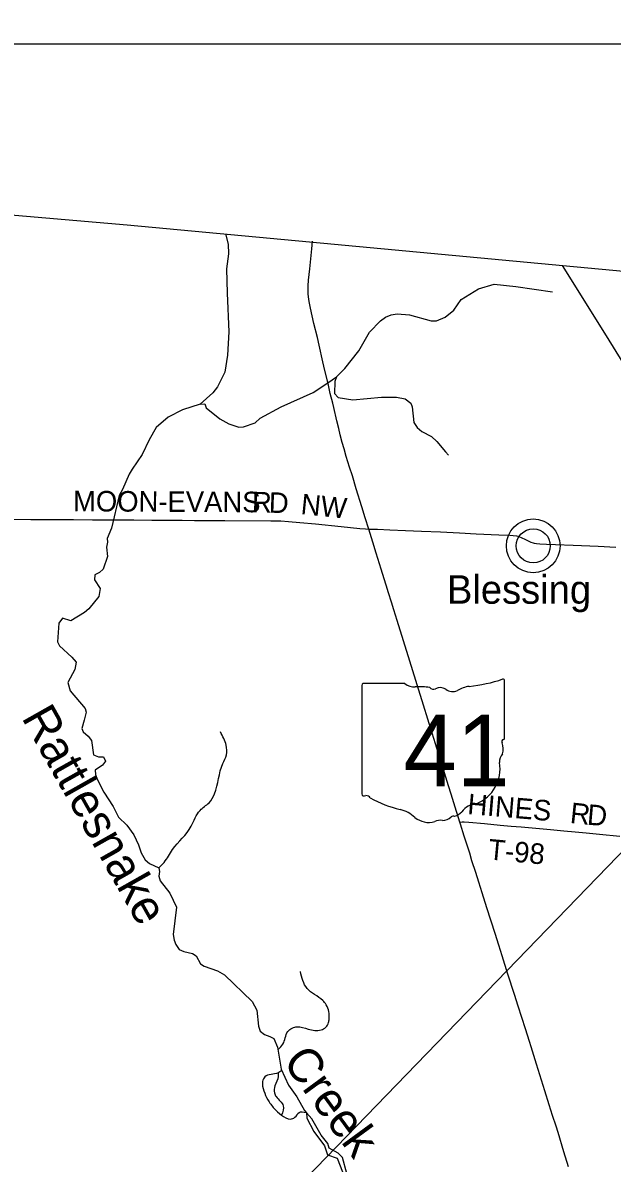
# Model space of a CAD drawing. Extents: x -49 to -8.2, y 9.4 to 23.5.
# Drawn here: x -41.499 to -40.683, y 19.456 to 21.033 of the extents above; entities that cross this region are included whole.
import ezdxf

# ---------------------------------------------------------------- set-up
doc = ezdxf.new("R2010")
doc.units = 0
for name, color, linetype in [('GM_X_Adjacent_County', 7, 'Continuous'), ('GM_X_County_Road', 7, 'Continuous'), ('GM_X_County_Road_Text', 7, 'Continuous'), ('GM_X_Major_River', 7, 'Continuous'), ('GM_X_Major_River_Text', 7, 'Continuous'), ('GM_X_Minor_River', 7, 'Continuous'), ('GM_X_Rail_Line', 7, 'Continuous'), ('GM_X_State_Route', 7, 'Continuous'), ('GM_X_State_Shield', 7, 'Continuous'), ('GM_X_Township_Road', 7, 'Continuous'), ('GM_X_Township_Road_Text', 7, 'Continuous'), ('GM_X_Unincorporated', 7, 'Continuous'), ('GM_X_Unincorporated_Text', 7, 'Continuous'), ('SC_Scratch1', 7, 'Continuous')]:
    doc.layers.add(name, color=color, linetype=linetype)

msp = doc.modelspace()

# ---------------------------------------------------------------- linework, layer by layer
at = {"layer": 'GM_X_Adjacent_County'}
for points in [[(-42.0989, 21.0039), (-42.1133, 20.8458), (-42.1156, 20.8206), (-41.9021, 20.8017), (-41.5804, 20.7732), (-41.3548, 20.7539), (-41.1025, 20.7304), (-40.4155, 20.6663), (-39.4895, 20.588)], [(-42.0989, 21.0039), (-42.1133, 20.8458), (-42.1156, 20.8206), (-41.9021, 20.8017), (-41.5804, 20.7732), (-41.3548, 20.7539), (-41.1025, 20.7304), (-40.4155, 20.6663), (-39.4895, 20.588)], [(-39.4895, 20.588), (-39.4895, 21.0039), (-42.0989, 21.0039)], [(-39.4895, 20.588), (-39.4895, 21.0039), (-42.0989, 21.0039)]]:
    msp.add_lwpolyline(points, dxfattribs=at)
at = {"layer": 'GM_X_County_Road'}
for points in [[(-41.5222, 20.3465), (-41.4881, 20.3462), (-41.454, 20.3461), (-41.4291, 20.346), (-41.4027, 20.3458), (-41.3888, 20.3457), (-41.3764, 20.3456), (-41.3624, 20.3456), (-41.3453, 20.3455), (-41.3205, 20.3453), (-41.2786, 20.3451), (-41.2615, 20.3449), (-41.2491, 20.3449), (-41.2196, 20.3447), (-41.156, 20.3444), (-41.142, 20.3441), (-41.1312, 20.3435), (-41.1157, 20.3421), (-41.0941, 20.34), (-41.0586, 20.3363), (-41.0324, 20.3338), (-41.0246, 20.3331), (-41.0203, 20.3327)], [(-41.0203, 20.3327), (-41.008, 20.3329), (-40.9909, 20.332), (-40.9692, 20.3311), (-40.9474, 20.3301), (-40.921, 20.3289), (-40.8947, 20.3275), (-40.8714, 20.3263), (-40.8403, 20.3251), (-40.8248, 20.3245), (-40.8202, 20.3241), (-40.8156, 20.3234), (-40.8126, 20.3226), (-40.8082, 20.321), (-40.804, 20.319), (-40.7985, 20.3161), (-40.7956, 20.3148), (-40.7927, 20.3138), (-40.7912, 20.3134), (-40.7882, 20.3128), (-40.7835, 20.3123), (-40.7742, 20.3119), (-40.7618, 20.3114), (-40.737, 20.3105), (-40.7028, 20.3091), (-40.678, 20.308)]]:
    msp.add_lwpolyline(points, dxfattribs=at)
at = {"layer": 'GM_X_Major_River'}
for points in [[(-41.2184, 20.7413), (-41.2148, 20.7272), (-41.2145, 20.7139), (-41.2171, 20.6928), (-41.2165, 20.6595), (-41.214, 20.6056), (-41.216, 20.5733), (-41.2195, 20.5502), (-41.2299, 20.5298), (-41.2362, 20.5213), (-41.2537, 20.5056), (-41.2783, 20.4978), (-41.2982, 20.4876), (-41.3144, 20.4735), (-41.3245, 20.4565), (-41.3339, 20.4362), (-41.348, 20.4156), (-41.352, 20.409), (-41.3612, 20.3877)], [(-41.3612, 20.3877), (-41.3659, 20.3793), (-41.3763, 20.3341), (-41.3825, 20.3197), (-41.3818, 20.3146), (-41.3834, 20.308), (-41.382, 20.2952), (-41.3882, 20.2776), (-41.393, 20.2728), (-41.3996, 20.2694), (-41.3999, 20.2628), (-41.3921, 20.2505), (-41.3941, 20.2397), (-41.4078, 20.2224), (-41.4138, 20.2177), (-41.4328, 20.2062), (-41.4445, 20.2095), (-41.4493, 20.2027), (-41.4512, 20.1769), (-41.4486, 20.1714), (-41.4314, 20.1555), (-41.4256, 20.1488), (-41.427, 20.1385), (-41.437, 20.1206), (-41.4339, 20.1092), (-41.4131, 20.0846), (-41.4117, 20.0795), (-41.4144, 20.0687), (-41.4175, 20.057), (-41.4157, 20.0522), (-41.4086, 20.0463), (-41.4043, 20.0403), (-41.4012, 20.0207), (-41.3946, 20.018), (-41.3876, 20.0178), (-41.3849, 20.0118), (-41.3891, 20.0064), (-41.3992, 19.9994), (-41.3988, 19.9934), (-41.3961, 19.9871), (-41.387, 19.9691), (-41.3743, 19.9491), (-41.3669, 19.9345)], [(-41.3669, 19.9345), (-41.3551, 19.9231), (-41.3457, 19.9101), (-41.339, 19.8962), (-41.3356, 19.8848), (-41.33, 19.8753), (-41.3238, 19.8701), (-41.311, 19.8644), (-41.3098, 19.8593), (-41.3108, 19.8526), (-41.3092, 19.8462), (-41.2958, 19.8294), (-41.2866, 19.81), (-41.291, 19.7722), (-41.2895, 19.7641), (-41.2873, 19.758), (-41.2826, 19.7515), (-41.2764, 19.7484), (-41.2643, 19.7459), (-41.2592, 19.7427), (-41.2534, 19.7316), (-41.2483, 19.7282), (-41.2299, 19.722), (-41.2199, 19.7163), (-41.1819, 19.6793), (-41.1751, 19.6673), (-41.1728, 19.6451), (-41.1708, 19.6384), (-41.1645, 19.6338), (-41.1572, 19.6309), (-41.1519, 19.6283), (-41.1465, 19.6163), (-41.1415, 19.5855), (-41.1312, 19.5638), (-41.1199, 19.5473), (-41.1091, 19.5284), (-41.1064, 19.5254)], [(-41.0507, 19.4412), (-41.0568, 19.4636), (-41.0628, 19.4694), (-41.0751, 19.4763), (-41.0767, 19.4827), (-41.0861, 19.4943), (-41.0989, 19.517), (-41.1064, 19.5254)], [(-41.1064, 19.5254), (-41.1061, 19.518), (-41.0963, 19.4993), (-41.0817, 19.4797), (-41.0772, 19.4673), (-41.0642, 19.4627), (-41.0565, 19.4439)]]:
    msp.add_lwpolyline(points, dxfattribs=at)
at = {"layer": 'GM_X_Minor_River'}
for points in [[(-41.2537, 20.5056), (-41.2474, 20.5064), (-41.2454, 20.5007), (-41.2265, 20.4854), (-41.214, 20.4787), (-41.2003, 20.4741), (-41.1936, 20.4744), (-41.1777, 20.4798), (-41.1707, 20.4863), (-41.1416, 20.5019), (-41.0972, 20.5221), (-41.0771, 20.5351), (-41.0647, 20.5436), (-41.0533, 20.5553), (-41.0339, 20.5795), (-41.0192, 20.6052), (-41.0041, 20.6211), (-40.9971, 20.6263), (-40.9893, 20.6295), (-40.9808, 20.6306), (-40.9638, 20.6294), (-40.9339, 20.6211), (-40.9264, 20.6209), (-40.9144, 20.6263), (-40.9024, 20.6359), (-40.8925, 20.6505), (-40.8682, 20.6653), (-40.8464, 20.6719), (-40.8165, 20.6685), (-40.7658, 20.661)], [(-41.0647, 20.5436), (-41.0672, 20.5372), (-41.0679, 20.5203), (-41.0624, 20.5151), (-41.0424, 20.5118), (-41.0028, 20.5154), (-40.982, 20.5153), (-40.9699, 20.5133)], [(-40.9699, 20.5133), (-40.962, 20.5069), (-40.9601, 20.5021), (-40.9576, 20.4805), (-40.9532, 20.4734), (-40.9466, 20.4679), (-40.9332, 20.461), (-40.9259, 20.4543), (-40.9142, 20.4397), (-40.9098, 20.4354)]]:
    msp.add_lwpolyline(points, dxfattribs=at)
for points in [[(-41.311, 19.8644), (-41.3037, 19.8718), (-41.2919, 19.8895), (-41.266, 19.9217), (-41.2539, 19.9438), (-41.2414, 19.9544), (-41.2338, 19.9667), (-41.2224, 20.0086), (-41.2174, 20.0207), (-41.2177, 20.0338), (-41.2257, 20.0524)], [(-41.1458, 19.6131), (-41.139, 19.6204), (-41.1323, 19.6378), (-41.1263, 19.6426), (-41.1192, 19.6444), (-41.1043, 19.6411), (-41.0861, 19.6401), (-41.0797, 19.6437), (-41.0759, 19.6503), (-41.0751, 19.655), (-41.0791, 19.6748), (-41.084, 19.6807), (-41.1057, 19.6975), (-41.1149, 19.7207)], [(-41.1408, 19.584), (-41.1459, 19.5806), (-41.1641, 19.575), (-41.1673, 19.5687), (-41.1655, 19.5558), (-41.1601, 19.5435), (-41.1513, 19.5315), (-41.1409, 19.5221), (-41.1288, 19.5166), (-41.1224, 19.5192), (-41.1168, 19.5258), (-41.1069, 19.5259)], [(-41.1459, 19.5806), (-41.1455, 19.5757), (-41.1503, 19.5626), (-41.1508, 19.5529), (-41.1485, 19.5478), (-41.1387, 19.535), (-41.1409, 19.5221)]]:
    msp.add_spline(points, degree=3, dxfattribs=at)
at = {"layer": 'GM_X_Rail_Line'}
msp.add_lwpolyline([(-40.6679, 20.5631), (-40.6912, 20.6002), (-40.7519, 20.6976)], dxfattribs=at)
at = {"layer": 'GM_X_State_Route'}
msp.add_lwpolyline([(-40.7435, 19.4504), (-40.7499, 19.4712), (-40.7581, 19.4979), (-40.7609, 19.5068), (-40.7656, 19.5216), (-40.7703, 19.5364), (-40.7763, 19.5557), (-40.7878, 19.5928), (-40.7952, 19.6166), (-40.7976, 19.6239), (-40.8034, 19.6417), (-40.8134, 19.6727), (-40.8186, 19.689), (-40.8275, 19.7171), (-40.8355, 19.7423), (-40.8402, 19.7571), (-40.8454, 19.7734), (-40.8568, 19.8089), (-40.8632, 19.8297), (-40.8679, 19.8445), (-40.8721, 19.8578), (-40.8773, 19.8741), (-40.8805, 19.8845), (-40.888, 19.9082), (-40.8931, 19.9246), (-40.894, 19.9276), (-40.9005, 19.9483), (-40.9061, 19.966), (-40.9098, 19.9779), (-40.9192, 20.0075), (-40.9278, 20.0357), (-40.9324, 20.0506), (-40.9366, 20.064), (-40.9461, 20.0951), (-40.9512, 20.1115), (-40.9549, 20.1233), (-40.9634, 20.15), (-40.9807, 20.2064), (-40.9854, 20.2212), (-40.9886, 20.2316), (-40.9929, 20.2449), (-40.9962, 20.2552), (-40.999, 20.2641), (-41.0031, 20.2775), (-41.01, 20.2997), (-41.0147, 20.3146), (-41.0203, 20.3327), (-41.0252, 20.3487), (-41.0298, 20.3635), (-41.0375, 20.3888), (-41.0429, 20.4066), (-41.0467, 20.4185), (-41.0513, 20.4333), (-41.0544, 20.4438), (-41.0569, 20.4527), (-41.0597, 20.4632), (-41.0619, 20.4723), (-41.0644, 20.4829), (-41.0688, 20.501), (-41.0702, 20.5071), (-41.0735, 20.5206), (-41.0766, 20.5343), (-41.0809, 20.5524), (-41.0837, 20.5645), (-41.089, 20.5872), (-41.0914, 20.5978), (-41.0961, 20.6174), (-41.101, 20.6386), (-41.1029, 20.6478), (-41.1038, 20.654), (-41.1042, 20.6586), (-41.1043, 20.6633), (-41.1041, 20.6696), (-41.1035, 20.6773), (-41.1019, 20.6928), (-41.0991, 20.7206), (-41.098, 20.7311)], dxfattribs=at)
at = {"layer": 'GM_X_State_Shield'}
for p, q in [((-41.0299, 20.1167), (-41.0299, 19.9666)), ((-40.9701, 20.1192), (-41.028, 20.1192)), ((-40.8322, 20.0444), (-40.8322, 20.123)), ((-40.8322, 20.0445), (-40.8322, 20.0444))]:
    msp.add_line(p, q, dxfattribs=at)
for centre, radius, start, end in [((-41.0277, 20.117), 0.00229, 98.1301, 188.1301), ((-40.9563, 20.1367), 0.0222, 231.6195, 271.1119), ((-40.9026, 20.3239), 0.2097, 275.8445, 288.9065), ((-40.8344, 20.1233), 0.0022, 351.8621, 97.738), ((-40.9489, 20.035), 0.0798, 80.4867, 94.9883), ((-40.9308, 20.1178), 0.00641, 219.7921, 297.1024), ((-40.9214, 20.1004), 0.0133, 54.4667, 119.1411), ((-40.9042, 20.1242), 0.016, 233.8562, 294.8282), ((-40.8759, 20.0734), 0.0422, 97.3462, 120.7689), ((-40.8327, 20.0387), 0.00341, 107.944, 210.337), ((-40.8544, 20.0288), 0.0205, 340.033, 23.6496), ((-40.8345, 20.0441), 0.00236, 289.6038, 7.7341), ((-40.8243, 20.0116), 0.0149, 136.8065, 186.9296), ((-40.8909, 20.0016), 0.0525, 292.3089, 8.9858), ((-41.0276, 19.9662), 0.00231, 171.9584, 258.3066), ((-41.0273, 19.9816), 0.0176, 267.339, 280.6039), ((-41.0237, 19.9579), 0.00636, 29.7484, 93.2717), ((-40.9434, 20.0928), 0.1514, 240.4129, 257.1985), ((-40.9885, 19.8991), 0.0474, 47.1842, 75.836), ((-40.8687, 19.9244), 0.0287, 94.4031, 142.5768), ((-40.9373, 19.9572), 0.0301, 230.7004, 286.2918), ((-40.9199, 19.9053), 0.0247, 85.6951, 111.2099), ((-40.9177, 19.9459), 0.016, 268.777, 315.5493), ((-40.9032, 19.9314), 0.00451, 65.7517, 132.6484), ((-40.9051, 19.952), 0.0169, 282.8732, 323.2771)]:
    msp.add_arc(centre, radius, start, end, dxfattribs=at)
at = {"layer": 'GM_X_Township_Road'}
msp.add_lwpolyline([(-40.894, 19.9276), (-40.8911, 19.9277), (-40.888, 19.9277), (-40.8817, 19.9274), (-40.8601, 19.9255), (-40.8384, 19.9234), (-40.8229, 19.9221), (-40.809, 19.9209), (-40.7888, 19.919), (-40.7687, 19.9173), (-40.7501, 19.9156), (-40.7346, 19.9142), (-40.7192, 19.9127), (-40.7006, 19.911), (-40.6727, 19.9083)], dxfattribs=at)
at = {"layer": 'GM_X_Unincorporated'}
for radius in [0.0372, 0.0236]:
    msp.add_circle((-40.7925, 20.3097), radius, dxfattribs=at)
at = {"layer": 'SC_Scratch1'}
msp.add_line((-48.2943, 12.0149), (-38.2371, 22.3973), dxfattribs=at)

# ---------------------------------------------------------------- texts
at = {"layer": 'GM_X_County_Road_Text'}
for s, height, rotation, p in [('MOON-EVANS', 0.02841, 359.6936, (-41.4298, 20.3575)), ('R', 0.0284, 358.7978, (-41.1822, 20.3562)), ('D', 0.0284, 357.8976, (-41.159, 20.3557)), ('NW', 0.02841, 354.2506, (-41.1152, 20.3537))]:
    msp.add_text(s, height=height, rotation=rotation, dxfattribs=at).set_placement(p)
at = {"layer": 'GM_X_Major_River_Text'}
for s, height, rotation, p in [('Rattlesnake', 0.047367, 299.4416, (-41.5017, 20.0722)), ('Creek', 0.04736, 306.1979, (-41.1406, 19.5961))]:
    msp.add_text(s, height=height, rotation=rotation, dxfattribs=at).set_placement(p)
at = {"layer": 'GM_X_State_Shield'}
msp.add_text('41', height=0.09888, dxfattribs=at).set_placement((-40.9721, 19.9772))
at = {"layer": 'GM_X_Township_Road_Text'}
for s, height, rotation, p in [('HINES', 0.02841, 355.1596, (-40.8843, 19.9387)), ('R', 0.0284, 354.0688, (-40.7424, 19.9265)), ('D', 0.0284, 354.9803, (-40.7187, 19.9241)), ('T-98', 0.02841, 354.7119, (-40.8557, 19.876))]:
    msp.add_text(s, height=height, rotation=rotation, dxfattribs=at).set_placement(p)
at = {"layer": 'GM_X_Unincorporated_Text'}
msp.add_text('Blessing', height=0.03949, rotation=0, dxfattribs=at).set_placement((-40.912, 20.2296))

doc.saveas('drawing.dxf')
